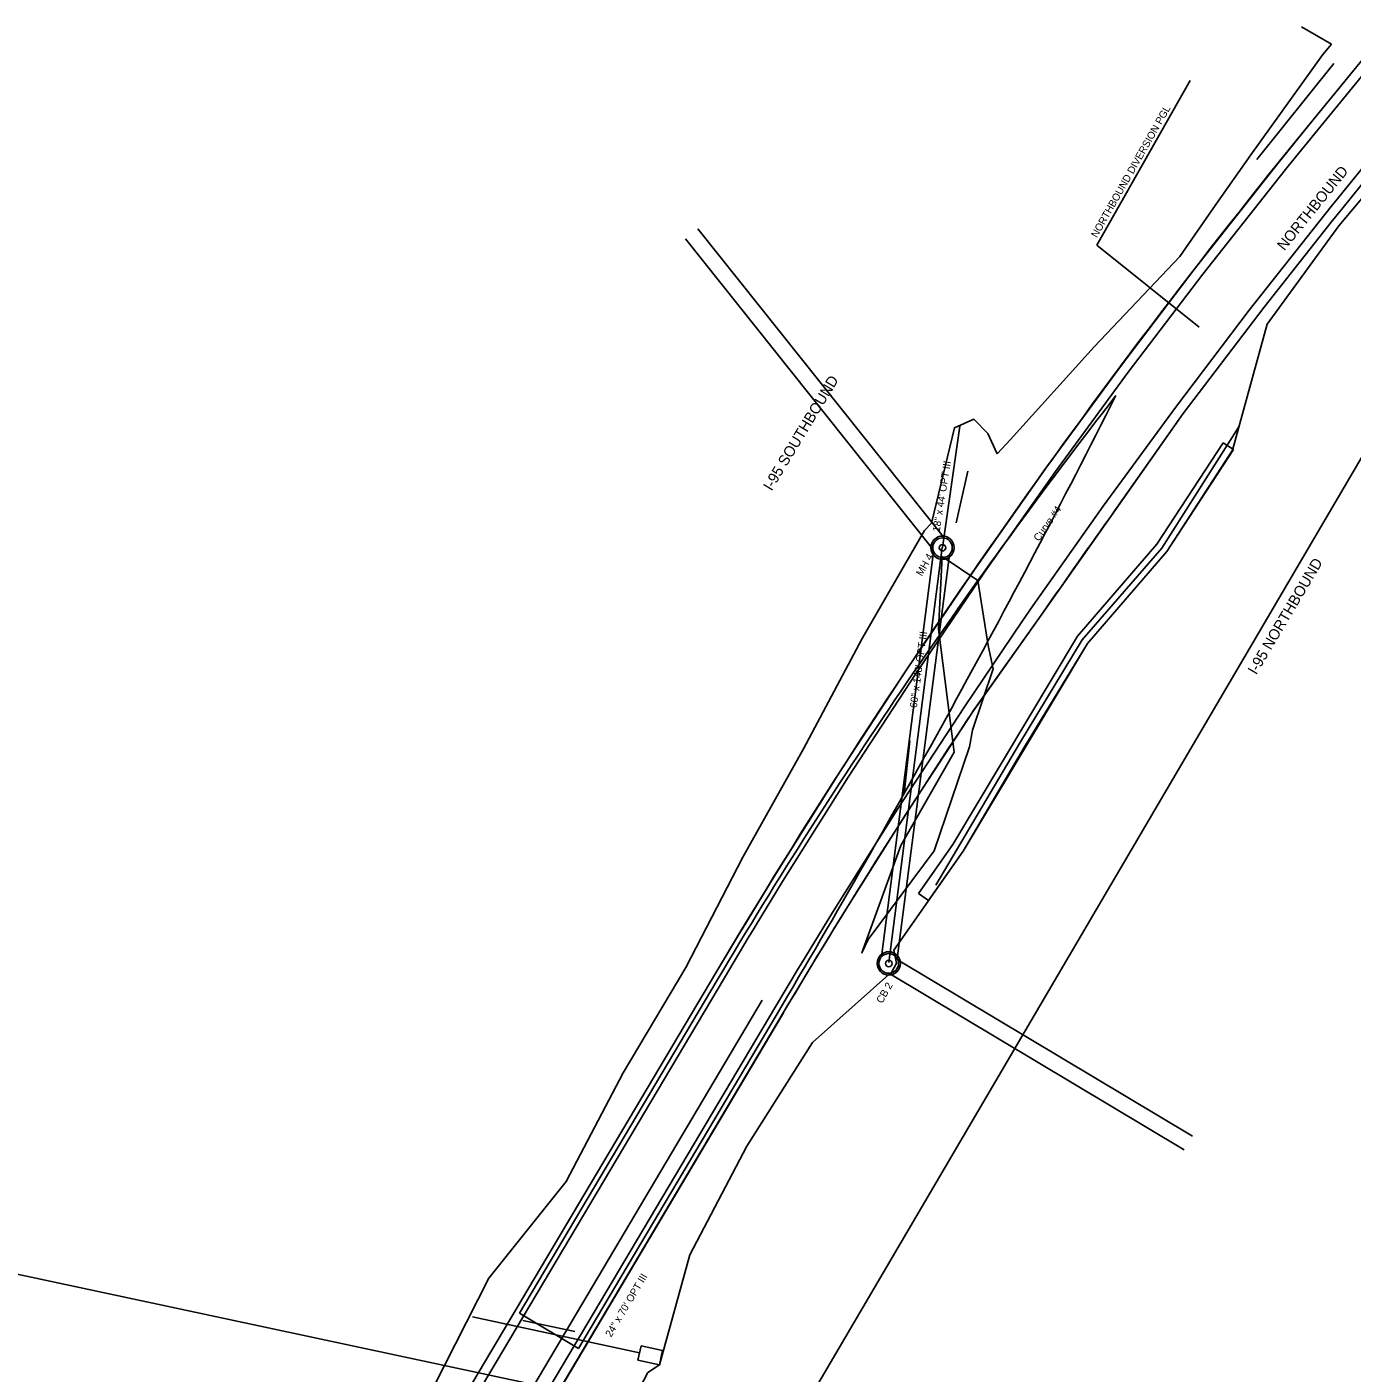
# Model space of a CAD drawing. Extents: x 1160458 to 1162290, y 615427 to 618737.
# Drawn here: x 1161114 to 1161654, y 617290 to 617839 of the extents above; entities that cross this region are included whole.
import ezdxf

# ---------------------------------------------------------------- set-up
doc = ezdxf.new("R2010")
doc.units = 0
for name, color, linetype in [('1', 7, 'Continuous'), ('_55 MPH DETOUR PVM SHARED', 7, 'Continuous'), ('ANNOTATION', 7, 'Continuous'), ('D_Drainage_Culvert', 7, 'Continuous'), ('D_Drainage_Ditch_Line', 7, 'Continuous'), ('D_Drainage_MH', 7, 'Continuous'), ('D_Drainage_RipRap', 7, 'Continuous'), ('D_Drainage_Text', 7, 'Continuous'), ('D_Guardrail_Beam_Lt', 7, 'Continuous'), ('D_Roadway_Centerline', 7, 'Continuous'), ('D_Roadway_Edge_Pavement', 7, 'Continuous'), ('D_Roadway_Edge_TW', 7, 'Continuous'), ('D_Slope_Cut', 7, 'Continuous'), ('D_Slope_Fill', 7, 'Continuous'), ('D_Text_Standard', 7, 'Continuous'), ('JUNK', 7, 'Continuous'), ('P_Driveway_Hatch', 7, 'Continuous'), ('S_Wetland_General', 7, 'Continuous')]:
    doc.layers.add(name, color=color, linetype=linetype)

msp = doc.modelspace()

# ---------------------------------------------------------------- linework, layer by layer
at = {"layer": '1'}
msp.add_line((1161209.81, 616899.51), (1162286.6, 618733.81), dxfattribs=at)
at = {"layer": '_55 MPH DETOUR PVM SHARED'}
for p, q in [((1161395.51, 617450.33), (1161314.87, 617314.55)), ((1161338.95, 617300.25), (1161419.59, 617436.04)), ((1161314.87, 617314.55), (1161338.95, 617300.25))]:
    msp.add_line(p, q, dxfattribs=at)
for centre, radius, start, end in [((1163367.9, 616278.96), 2294, 142.08263, 149.29443), ((1157796.38, 619587.82), 4214, 329.29443, 333.21306)]:
    msp.add_arc(centre, radius, start, end, dxfattribs=at)
at = {"layer": 'D_Drainage_Culvert'}
for p, q in [((1161487.42, 617626.72), (1161494.48, 617676.25)), ((1161487.32, 617626.71), (1161465.51, 617457.62)), ((1161295.72, 617313.16), (1161363.87, 617298.39))]:
    msp.add_line(p, q, dxfattribs=at)
at = {"layer": 'D_Drainage_Ditch_Line'}
msp.add_line((1161647.03, 617824.06), (1161615.58, 617784.92), dxfattribs=at)
msp.add_lwpolyline([(1161484.78, 617489.15), (1161518.79, 617546.87), (1161544.4, 617589.11), (1161576.85, 617626.55), (1161608.23, 617675.92)], dxfattribs=at)
at = {"layer": 'D_Drainage_MH'}
for centre in [(1161487.44, 617626.7), (1161465.52, 617457.21)]:
    msp.add_circle(centre, 1.33, dxfattribs=at)
at = {"layer": 'D_Drainage_RipRap'}
for p, q in [((1161606.11, 617666.66), (1161578.88, 617625.09)), ((1161601.93, 617669.4), (1161606.11, 617666.66)), ((1161578.88, 617625.09), (1161546.51, 617587.64)), ((1161546.51, 617587.64), (1161495.86, 617503)), ((1161495.86, 617503), (1161481.74, 617482.8)), ((1161481.74, 617482.8), (1161477.64, 617485.66)), ((1161363.23, 617295.46), (1161364.51, 617301.32)), ((1161373.3, 617299.42), (1161364.51, 617301.32)), ((1161372.03, 617293.55), (1161373.3, 617299.42)), ((1161372.03, 617293.55), (1161363.23, 617295.46))]:
    msp.add_line(p, q, dxfattribs=at)
msp.add_lwpolyline([(1161477.64, 617485.66), (1161491.66, 617505.72), (1161542.44, 617590.58), (1161574.88, 617628.11), (1161601.93, 617669.4)], dxfattribs=at)
msp.add_lwpolyline([(1161364.51, 617301.32), (1161363.23, 617295.46), (1161372.03, 617293.55), (1161373.3, 617299.42)], close=True, dxfattribs=at)
at = {"layer": 'D_Guardrail_Beam_Lt'}
for p, q in [((1161723.42, 617904.81), (1161637.37, 617799.61)), ((1161499.72, 617559.72), (1161528.37, 617600.13)), ((1161395.02, 617453.42), (1161206.29, 617135.63)), ((1161233.79, 617119.3), (1161422.52, 617437.09))]:
    msp.add_line(p, q, dxfattribs=at)
msp.add_lwpolyline([(1161557.08, 617640.92), (1161585.62, 617681.47)], dxfattribs=at)
for radius, start, end in [(2826, 140.71863, 149.29443), (2793.02, 144.28596, 145.30546), (2794.02, 146.32496, 149.29443)]:
    msp.add_arc((1163824.82, 616010.39), radius, start, end, dxfattribs=at)
at = {"layer": 'D_Roadway_Centerline'}
msp.add_line((1160573.57, 617445.06), (1162040.51, 617131.87), dxfattribs=at)
at = {"layer": 'D_Roadway_Edge_Pavement'}
for points in [[(1161618.68, 617724.81), (1161646.49, 617760.08), (1161649.61, 617763.95), (1161650.23, 617764.73), (1161662.12, 617779.35), (1161748.17, 617884.56), (1161757.13, 617895.56), (1161758.72, 617897.51), (1161772.9, 617915.08), (1161804.08, 617954.41), (1161834.79, 617994.11), (1161855.07, 618020.99)], [(1161206.3, 617135.62), (1161395.03, 617453.42), (1161405.18, 617470.36), (1161405.7, 617471.22), (1161418.79, 617492.69), (1161445.54, 617535.26), (1161473.05, 617577.36), (1161497.02, 617612.75), (1161501.3, 617618.95), (1161530.29, 617660.04), (1161560.01, 617700.6), (1161590.44, 617740.63), (1161621.58, 617780.11), (1161624.73, 617784.03), (1161625.36, 617784.81), (1161637.38, 617799.61), (1161723.43, 617904.81)], [(1161499.65, 617559.62), (1161528.37, 617600.13), (1161557.3, 617641.23), (1161585.62, 617681.47), (1161618.68, 617724.81)], [(1161191.85, 617046.2), (1161216.32, 617089.48), (1161223.81, 617102.37), (1161224.32, 617103.23), (1161233.79, 617119.31), (1161422.51, 617437.08), (1161432.54, 617453.83), (1161433.05, 617454.68), (1161446, 617475.9), (1161472.45, 617517.99), (1161499.64, 617559.61), (1161499.65, 617559.62)]]:
    msp.add_lwpolyline(points, dxfattribs=at)
at = {"layer": 'D_Roadway_Edge_TW'}
for points in [[(1161209.73, 617133.6), (1161398.46, 617451.37), (1161408.59, 617468.3), (1161409.1, 617469.15), (1161422.17, 617490.58), (1161448.9, 617533.1), (1161476.37, 617575.14), (1161500.31, 617610.48), (1161504.57, 617616.66), (1161533.53, 617657.7), (1161563.2, 617698.21), (1161593.59, 617738.18), (1161624.69, 617777.62), (1161627.83, 617781.52), (1161628.46, 617782.3), (1161640.47, 617797.08), (1161726.52, 617902.28)], [(1161230.36, 617121.33), (1161419.1, 617439.13), (1161429.13, 617455.89), (1161429.65, 617456.75), (1161442.62, 617478.01), (1161469.1, 617520.15), (1161496.34, 617561.83), (1161520.06, 617596.86), (1161524.32, 617603.02), (1161553.01, 617643.69), (1161582.43, 617683.86), (1161612.56, 617723.49), (1161643.38, 617762.57), (1161646.51, 617766.46), (1161647.14, 617767.24), (1161659.04, 617781.88)]]:
    msp.add_lwpolyline(points, dxfattribs=at)
at = {"layer": 'D_Slope_Cut'}
for p, q in [((1161633.82, 617839.01), (1161646.1, 617831.93)), ((1161468.66, 617457.33), (1161467.62, 617462.59))]:
    msp.add_line(p, q, dxfattribs=at)
for points in [[(1161598.68, 617766.14), (1161613.12, 617786.9), (1161642.58, 617827.7), (1161646.1, 617831.93)], [(1161482.9, 617636.64), (1161492.3, 617675.6), (1161500.2, 617679.08), (1161505.88, 617673.29), (1161509.69, 617665)]]:
    msp.add_lwpolyline(points, dxfattribs=at)
at = {"layer": 'D_Slope_Fill'}
for points in [[(1161467.62, 617462.59), (1161495.86, 617503), (1161520.87, 617545.48), (1161546.51, 617587.64), (1161578.88, 617625.09), (1161605.67, 617666.51), (1161619.85, 617717.84), (1161649.13, 617757.97), (1161681.16, 617796.15), (1161720.89, 617828.25), (1161750.61, 617868.53), (1161779.17, 617910.05), (1161801.48, 617942.93), (1161821.11, 617976.43)], [(1161509.69, 617665), (1161515.22, 617670.86), (1161549.32, 617708.57), (1161584.26, 617745.4), (1161598.68, 617766.14)], [(1161246.79, 617244.96), (1161271.11, 617267.77), (1161279.77, 617284.18), (1161302.44, 617328.86), (1161333.99, 617368.28), (1161357.23, 617412.63), (1161382.77, 617455.61), (1161406.02, 617500.54), (1161430.73, 617544.75), (1161454.64, 617589.61), (1161480.07, 617633.64), (1161482.9, 617636.64)], [(1161308.53, 617208.94), (1161338.28, 617249.42), (1161346.17, 617250.06), (1161367.25, 617290.37), (1161372.03, 617293.55), (1161384.4, 617338.34), (1161407.67, 617382.67), (1161434.38, 617424.96), (1161466.71, 617453.8), (1161468.72, 617457.3)]]:
    msp.add_lwpolyline(points, dxfattribs=at)
at = {"layer": 'D_Text_Standard'}
for p, q in [((1161550.37, 617750), (1161588.45, 617817.13)), ((1161550.37, 617750), (1161592.1, 617716.57)), ((1161497.73, 617657.9), (1161493.05, 617636.83)), ((1161474.13, 617547.92), (1161471.75, 617526.48)), ((1161316.32, 617311.58), (1161337.45, 617307.19))]:
    msp.add_line(p, q, dxfattribs=at)
at = {"layer": 'JUNK'}
for p, q in [((1161488.22, 617630.62), (1161387.7, 617756.64)), ((1161483.48, 617626.15), (1161382.61, 617752.58)), ((1161483.82, 617624.99), (1161462.52, 617459.85)), ((1161490.22, 617623.83), (1161468.99, 617459.2)), ((1161469.29, 617458.55), (1161589.33, 617386.74)), ((1161465.55, 617453.21), (1161585.99, 617381.16))]:
    msp.add_line(p, q, dxfattribs=at)
for centre, radius in [((1161487.44, 617626.7), 4.75), ((1161487.44, 617626.7), 4), ((1161465.52, 617457.21), 4.75), ((1161465.52, 617457.21), 4)]:
    msp.add_circle(centre, radius, dxfattribs=at)
at = {"layer": 'P_Driveway_Hatch'}
msp.add_line((1161225.21, 617124.4), (1161413.94, 617442.18), dxfattribs=at)
at = {"layer": 'S_Wetland_General'}
msp.add_lwpolyline([(1161487.23, 617623.06), (1161501.88, 617613.31), (1161506.07, 617586.79), (1161508.09, 617577.35), (1161499.65, 617552.27), (1161498.41, 617545.49), (1161484.03, 617503.09), (1161457.06, 617466.96), (1161454.57, 617461.47), (1161470.44, 617505.34), (1161492.22, 617543.32), (1161485.85, 617593.44)], close=True, dxfattribs=at)

# ---------------------------------------------------------------- texts
at = {"layer": 'ANNOTATION'}
msp.add_text('Curve #4', height=3, rotation=54.8046, dxfattribs=at).set_placement((1161526.74, 617629.06))
at = {"layer": 'D_Drainage_Text'}
for s, rotation, p in [('18" x 44\' OPT III', 80.9803, (1161486.29, 617633.04)), ('MH 4', 60.1613, (1161479.01, 617614.86)), ('60" x 148\' OPT III', 82.2648, (1161476.96, 617561.26)), ('CB 2', 60.1613, (1161462.82, 617440.64)), ('24" x 70\' OPT III', 59.1794, (1161352.25, 617304.58))]:
    msp.add_text(s, height=3, rotation=rotation, dxfattribs=at).set_placement(p)
at = {"layer": 'D_Text_Standard'}
for s, height, rotation, p in [('NORTHBOUND DIVERSION PGL', 3, 60.4348, (1161550.43, 617752.83)), ('NORTHBOUND', 4.375, 51.1589, (1161626.89, 617747.49)), ('I-95 SOUTHBOUND', 4.375, 58.9419, (1161417.74, 617649.54)), ('I-95 NORTHBOUND', 4.375, 59.4562, (1161615.4, 617574.6))]:
    msp.add_text(s, height=height, rotation=rotation, dxfattribs=at).set_placement(p)

doc.saveas('drawing.dxf')
